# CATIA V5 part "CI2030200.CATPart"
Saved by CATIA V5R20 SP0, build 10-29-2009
Part number: CI2030200
Bounding box of the stored display mesh (mm): x -29 to 29, y -24.37 to 245, z -40.082 to 32.547
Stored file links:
  C:\Users\Raffaele\Desktop\3D X SITO CF\BOLEX\19-INCLINED ASSEMBLY REF_CI\CI2030200.CATPart
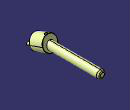
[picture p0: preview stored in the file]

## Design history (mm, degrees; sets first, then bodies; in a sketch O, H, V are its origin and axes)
Set1
  DatumSurface1 to DatumSurface16 "MANIFOLD_SOLID_BREP #397"
  DatumSurface17 to DatumSurface39 "MANIFOLD_SOLID_BREP #1146"
Body1 (main body)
